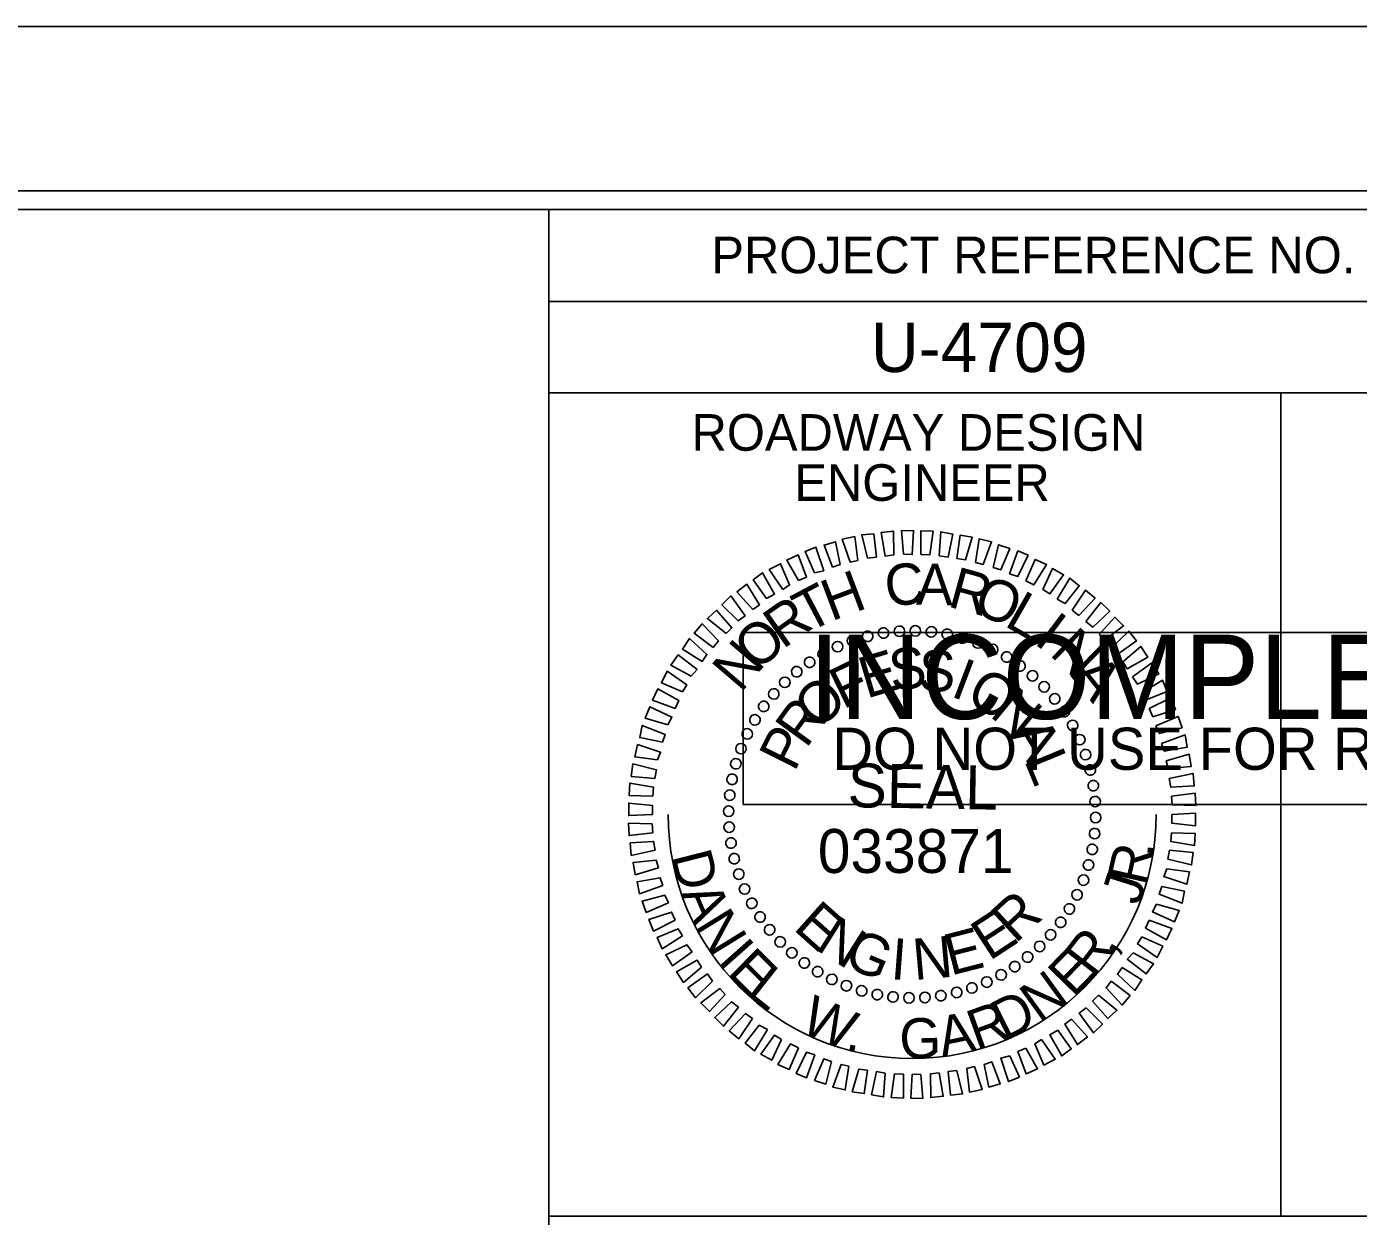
# Model space of a CAD drawing. Extents: x 958711 to 962106, y 831169 to 840840.
# Drawn here: x 960106.3 to 960288.4, y 840677.2 to 840839.7 of the extents above; entities that cross this region are included whole.
import ezdxf

# ---------------------------------------------------------------- set-up
doc = ezdxf.new("R2010")
doc.units = 0
for name, color, linetype in [('Scratch_Level_0', 7, 'Continuous'), ('Sheet Data Field CELL', 7, 'Continuous'), ('Sheet Plot Border Inside CELL', 7, 'Continuous'), ('Sheet Plot Border Outside CELL', 7, 'Continuous'), ('Sheet Professional Seal CELL', 7, 'Continuous'), ('Sheet Profile Grid Minor CELL', 7, 'Continuous'), ('Sheet Sticker Exception Certification CELL', 7, 'Continuous'), ('Sheet Sticker Incomplete CELL', 7, 'Continuous'), ('Sheet Typical CELL', 7, 'Continuous')]:
    doc.layers.add(name, color=color, linetype=linetype)

msp = doc.modelspace()

# ---------------------------------------------------------------- linework, layer by layer
at = {"layer": 'Scratch_Level_0'}
msp.add_arc((960227.41, 840732.08), 33.36, 180, 360, dxfattribs=at)
at = {"layer": 'Sheet Plot Border Inside CELL'}
msp.add_lwpolyline([(960390.3, 840817.27), (958723.8, 840817.27), (958723.8, 839762.17), (960390.3, 839762.17)], close=True, dxfattribs=at)
at = {"layer": 'Sheet Plot Border Outside CELL'}
msp.add_lwpolyline([(960394.8, 840839.72), (958710.8, 840839.72), (958710.8, 839739.72), (960394.8, 839739.72)], close=True, dxfattribs=at)
at = {"layer": 'Sheet Professional Seal CELL'}
for p, q in [((960221.31, 840756.43), (960221.31, 840756.43)), ((960223.51, 840756.83), (960223.51, 840756.83)), ((960225.66, 840757.13), (960225.66, 840757.13)), ((960227.86, 840757.18), (960227.86, 840757.18)), ((960230.06, 840757.03), (960230.06, 840757.03)), ((960232.21, 840756.68), (960232.21, 840756.68)), ((960217.21, 840755.03), (960217.21, 840755.03)), ((960219.21, 840755.83), (960219.21, 840755.83)), ((960234.31, 840756.23), (960234.31, 840756.23)), ((960236.41, 840755.53), (960236.41, 840755.53)), ((960238.41, 840754.63), (960238.41, 840754.63)), ((960213.36, 840752.88), (960213.36, 840752.88)), ((960215.26, 840754.03), (960215.26, 840754.03)), ((960240.36, 840753.63), (960240.36, 840753.63)), ((960211.61, 840751.63), (960211.61, 840751.63)), ((960242.16, 840752.38), (960242.16, 840752.38)), ((960243.91, 840751.03), (960243.91, 840751.03)), ((960209.96, 840750.13), (960209.96, 840750.13)), ((960245.46, 840749.53), (960245.46, 840749.53)), ((960208.46, 840748.58), (960208.46, 840748.58)), ((960246.96, 840747.88), (960246.96, 840747.88)), ((960207.11, 840746.83), (960207.11, 840746.83)), ((960248.21, 840746.13), (960248.21, 840746.13)), ((960205.86, 840745.03), (960205.86, 840745.03)), ((960249.36, 840744.23), (960249.36, 840744.23)), ((960204.86, 840743.08), (960204.86, 840743.08)), ((960250.36, 840742.28), (960250.36, 840742.28)), ((960203.96, 840741.08), (960203.96, 840741.08)), ((960251.16, 840740.28), (960251.16, 840740.28)), ((960203.26, 840738.98), (960203.26, 840738.98)), ((960251.76, 840738.18), (960251.76, 840738.18)), ((960202.81, 840736.88), (960202.81, 840736.88)), ((960202.46, 840734.73), (960202.46, 840734.73)), ((960252.16, 840735.98), (960252.16, 840735.98)), ((960252.46, 840733.83), (960252.46, 840733.83)), ((960202.31, 840732.53), (960202.31, 840732.53)), ((960227.41, 840732.08), (960227.41, 840732.08)), ((960252.51, 840731.63), (960252.51, 840731.63)), ((960202.36, 840730.33), (960202.36, 840730.33)), ((960252.36, 840729.43), (960252.36, 840729.43)), ((960202.66, 840728.18), (960202.66, 840728.18)), ((960252.01, 840727.28), (960252.01, 840727.28)), ((960203.06, 840725.98), (960203.06, 840725.98)), ((960203.66, 840723.88), (960203.66, 840723.88)), ((960251.56, 840725.18), (960251.56, 840725.18)), ((960204.46, 840721.88), (960204.46, 840721.88)), ((960250.86, 840723.08), (960250.86, 840723.08)), ((960205.46, 840719.93), (960205.46, 840719.93)), ((960249.96, 840721.08), (960249.96, 840721.08)), ((960206.61, 840718.03), (960206.61, 840718.03)), ((960248.96, 840719.13), (960248.96, 840719.13)), ((960207.86, 840716.28), (960207.86, 840716.28)), ((960247.71, 840717.33), (960247.71, 840717.33)), ((960209.36, 840714.63), (960209.36, 840714.63)), ((960246.36, 840715.58), (960246.36, 840715.58)), ((960210.91, 840713.13), (960210.91, 840713.13)), ((960244.86, 840714.03), (960244.86, 840714.03)), ((960212.66, 840711.78), (960212.66, 840711.78)), ((960241.46, 840711.28), (960241.46, 840711.28)), ((960243.21, 840712.53), (960243.21, 840712.53)), ((960214.46, 840710.53), (960214.46, 840710.53)), ((960216.41, 840709.53), (960216.41, 840709.53)), ((960237.61, 840709.13), (960237.61, 840709.13)), ((960239.56, 840710.13), (960239.56, 840710.13)), ((960218.41, 840708.63), (960218.41, 840708.63)), ((960220.51, 840707.93), (960220.51, 840707.93)), ((960222.61, 840707.48), (960222.61, 840707.48)), ((960224.76, 840707.13), (960224.76, 840707.13)), ((960231.31, 840707.33), (960231.31, 840707.33)), ((960233.51, 840707.73), (960233.51, 840707.73)), ((960235.61, 840708.33), (960235.61, 840708.33)), ((960226.96, 840706.98), (960226.96, 840706.98)), ((960229.16, 840707.03), (960229.16, 840707.03))]:
    msp.add_line(p, q, dxfattribs=at)
for points in [[(960226.21, 840767.63), (960225.96, 840770.88), (960227.61, 840770.83), (960227.41, 840767.58)], [(960228.61, 840767.58), (960228.61, 840770.83), (960230.26, 840770.78), (960229.81, 840767.53)], [(960216.51, 840765.88), (960215.36, 840768.88), (960216.91, 840769.33), (960217.56, 840766.23)], [(960218.91, 840766.53), (960217.86, 840769.68), (960219.56, 840770.03), (960219.96, 840766.78)], [(960221.31, 840767.08), (960220.51, 840770.28), (960222.16, 840770.43), (960222.51, 840767.23)], [(960223.71, 840767.38), (960223.16, 840770.58), (960224.86, 840770.78), (960224.91, 840767.53)], [(960231.11, 840767.43), (960231.31, 840770.68), (960232.96, 840770.38), (960232.31, 840767.23)], [(960233.51, 840767.03), (960233.96, 840770.23), (960235.61, 840769.98), (960234.71, 840766.88)], [(960236.06, 840766.48), (960236.56, 840769.73), (960238.26, 840769.33), (960237.11, 840766.23)], [(960211.86, 840764.03), (960210.26, 840766.83), (960211.81, 840767.53), (960212.96, 840764.48)], [(960214.06, 840765.08), (960212.76, 840767.98), (960214.26, 840768.58), (960215.31, 840765.38)], [(960238.46, 840765.83), (960239.21, 840768.93), (960240.76, 840768.43), (960239.51, 840765.48)], [(960240.71, 840764.93), (960241.86, 840768.08), (960243.26, 840767.48), (960241.86, 840764.58)], [(960209.71, 840762.83), (960207.86, 840765.53), (960209.41, 840766.33), (960210.66, 840763.43)], [(960242.96, 840763.98), (960244.21, 840766.93), (960245.76, 840766.23), (960244.06, 840763.43)], [(960245.26, 840762.83), (960246.61, 840765.68), (960248.11, 840764.83), (960246.21, 840762.23)], [(960205.61, 840760.08), (960203.46, 840762.48), (960204.81, 840763.53), (960206.56, 840760.73)], [(960207.51, 840761.58), (960205.66, 840764.13), (960206.96, 840765.08), (960208.61, 840762.18)], [(960247.21, 840761.48), (960248.96, 840764.38), (960250.26, 840763.33), (960248.31, 840760.88)], [(960203.61, 840758.53), (960201.41, 840760.73), (960202.61, 840761.93), (960204.56, 840759.23)], [(960249.26, 840759.98), (960251.11, 840762.73), (960252.41, 840761.63), (960250.21, 840759.28)], [(960201.96, 840756.78), (960199.41, 840758.83), (960200.66, 840759.98), (960202.76, 840757.58)], [(960251.16, 840758.43), (960253.21, 840761.03), (960254.41, 840759.83), (960252.11, 840757.68)], [(960200.21, 840754.88), (960197.61, 840756.83), (960198.71, 840758.13), (960200.91, 840755.78)], [(960252.96, 840756.68), (960255.11, 840759.03), (960256.31, 840757.83), (960253.71, 840755.88)], [(960254.71, 840754.88), (960257.01, 840757.13), (960258.06, 840755.78), (960255.41, 840753.88)], [(960198.71, 840752.98), (960196.01, 840754.68), (960196.96, 840756.13), (960199.36, 840753.93)], [(960256.21, 840752.93), (960258.66, 840755.03), (960259.61, 840753.58), (960256.81, 840751.98)], [(960197.21, 840750.98), (960194.41, 840752.48), (960195.41, 840753.88), (960198.01, 840751.88)], [(960257.51, 840750.88), (960260.16, 840752.78), (960261.11, 840751.28), (960258.21, 840749.88)], [(960196.01, 840748.83), (960193.16, 840750.08), (960193.91, 840751.63), (960196.61, 840749.78)], [(960195.01, 840746.53), (960191.91, 840747.68), (960192.66, 840749.23), (960195.51, 840747.63)], [(960258.81, 840748.68), (960261.61, 840750.43), (960262.26, 840748.88), (960259.41, 840747.73)], [(960259.81, 840746.53), (960262.76, 840748.03), (960263.41, 840746.43), (960260.31, 840745.43)], [(960194.01, 840744.33), (960190.91, 840745.23), (960191.56, 840746.78), (960194.56, 840745.38)], [(960260.71, 840744.18), (960263.76, 840745.48), (960264.31, 840743.93), (960261.21, 840743.13)], [(960193.26, 840741.93), (960190.16, 840742.58), (960190.51, 840744.23), (960193.66, 840742.98)], [(960261.51, 840741.78), (960264.71, 840742.93), (960265.01, 840741.28), (960261.86, 840740.73)], [(960192.61, 840739.53), (960189.51, 840739.93), (960189.86, 840741.63), (960193.01, 840740.58)], [(960262.11, 840739.38), (960265.26, 840740.33), (960265.56, 840738.63), (960262.41, 840738.33)], [(960192.21, 840736.98), (960189.01, 840737.28), (960189.21, 840738.98), (960192.46, 840738.18)], [(960191.96, 840734.58), (960188.71, 840734.68), (960188.81, 840736.33), (960192.06, 840735.78)], [(960262.56, 840736.98), (960265.81, 840737.68), (960265.96, 840735.98), (960262.76, 840735.78)], [(960262.86, 840734.58), (960266.11, 840734.98), (960266.21, 840733.28), (960262.96, 840733.38)], [(960191.91, 840732.08), (960188.66, 840731.93), (960188.66, 840733.63), (960191.91, 840733.28)], [(960191.96, 840729.58), (960188.71, 840729.18), (960188.61, 840730.88), (960191.86, 840730.78)], [(960262.91, 840732.08), (960266.16, 840732.23), (960266.16, 840730.53), (960262.91, 840730.88)], [(960262.86, 840729.58), (960266.11, 840729.48), (960266.01, 840727.83), (960262.76, 840728.38)], [(960192.26, 840727.18), (960189.01, 840726.48), (960188.86, 840728.18), (960192.06, 840728.38)], [(960262.61, 840727.18), (960265.81, 840726.88), (960265.61, 840725.18), (960262.36, 840725.98)], [(960192.71, 840724.78), (960189.56, 840723.83), (960189.26, 840725.53), (960192.41, 840725.83)], [(960262.21, 840724.63), (960265.31, 840724.23), (960264.96, 840722.53), (960261.81, 840723.58)], [(960193.31, 840722.38), (960190.11, 840721.23), (960189.81, 840722.88), (960192.96, 840723.43)], [(960261.56, 840722.23), (960264.66, 840721.58), (960264.31, 840719.93), (960261.16, 840721.18)], [(960194.11, 840719.98), (960191.06, 840718.68), (960190.51, 840720.23), (960193.61, 840721.03)], [(960260.81, 840719.83), (960263.91, 840718.93), (960263.26, 840717.38), (960260.26, 840718.78)], [(960195.01, 840717.63), (960192.06, 840716.13), (960191.41, 840717.73), (960194.51, 840718.73)], [(960196.01, 840715.48), (960193.21, 840713.73), (960192.56, 840715.28), (960195.41, 840716.43)], [(960259.81, 840717.63), (960262.91, 840716.48), (960262.16, 840714.93), (960259.31, 840716.53)], [(960258.81, 840715.33), (960261.66, 840714.08), (960260.91, 840712.53), (960258.21, 840714.38)], [(960197.31, 840713.28), (960194.66, 840711.38), (960193.71, 840712.88), (960196.61, 840714.28)], [(960257.61, 840713.18), (960260.41, 840711.68), (960259.41, 840710.28), (960256.81, 840712.28)], [(960198.61, 840711.23), (960196.16, 840709.13), (960195.21, 840710.58), (960198.01, 840712.18)], [(960256.11, 840711.18), (960258.81, 840709.48), (960257.86, 840708.03), (960255.46, 840710.23)], [(960200.11, 840709.28), (960197.81, 840707.03), (960196.76, 840708.38), (960199.41, 840710.28)], [(960254.61, 840709.28), (960257.21, 840707.33), (960256.11, 840706.03), (960253.91, 840708.38)], [(960201.86, 840707.48), (960199.71, 840705.13), (960198.51, 840706.33), (960201.11, 840708.28)], [(960252.86, 840707.38), (960255.41, 840705.33), (960254.16, 840704.18), (960252.06, 840706.58)], [(960203.66, 840705.73), (960201.61, 840703.13), (960200.41, 840704.33), (960202.71, 840706.48)], [(960251.21, 840705.63), (960253.41, 840703.43), (960252.21, 840702.23), (960250.26, 840704.93)], [(960205.56, 840704.18), (960203.71, 840701.43), (960202.41, 840702.53), (960204.61, 840704.88)], [(960249.21, 840704.08), (960251.36, 840701.68), (960250.01, 840700.63), (960248.26, 840703.43)], [(960207.61, 840702.68), (960205.86, 840699.78), (960204.56, 840700.83), (960206.51, 840703.28)], [(960209.56, 840701.33), (960208.21, 840698.48), (960206.71, 840699.33), (960208.61, 840701.93)], [(960247.31, 840702.58), (960249.16, 840700.03), (960247.86, 840699.08), (960246.21, 840701.98)], [(960211.86, 840700.18), (960210.61, 840697.23), (960209.06, 840697.93), (960210.76, 840700.73)], [(960242.96, 840700.13), (960244.56, 840697.33), (960243.01, 840696.63), (960241.86, 840699.68)], [(960245.11, 840701.33), (960246.96, 840698.63), (960245.41, 840697.83), (960244.16, 840700.73)], [(960214.11, 840699.23), (960212.96, 840696.08), (960211.56, 840696.68), (960212.96, 840699.58)], [(960216.36, 840698.33), (960215.61, 840695.23), (960214.06, 840695.73), (960215.31, 840698.68)], [(960238.31, 840698.28), (960239.46, 840695.28), (960237.91, 840694.83), (960237.26, 840697.93)], [(960240.76, 840699.08), (960242.06, 840696.18), (960240.56, 840695.58), (960239.51, 840698.78)], [(960218.76, 840697.68), (960218.26, 840694.43), (960216.56, 840694.83), (960217.71, 840697.93)], [(960221.31, 840697.13), (960220.86, 840693.93), (960219.21, 840694.18), (960220.11, 840697.28)], [(960223.71, 840696.73), (960223.51, 840693.48), (960221.86, 840693.78), (960222.51, 840696.93)], [(960226.21, 840696.58), (960226.21, 840693.33), (960224.56, 840693.38), (960225.01, 840696.63)], [(960228.61, 840696.53), (960228.86, 840693.28), (960227.21, 840693.33), (960227.41, 840696.58)], [(960231.11, 840696.78), (960231.66, 840693.58), (960229.96, 840693.38), (960229.91, 840696.63)], [(960233.51, 840697.08), (960234.31, 840693.88), (960232.66, 840693.73), (960232.31, 840696.93)], [(960235.91, 840697.63), (960236.96, 840694.48), (960235.26, 840694.13), (960234.86, 840697.38)]]:
    msp.add_lwpolyline(points, close=True, dxfattribs=at)
for centre, major_axis in [((960219.25, 840755.8), (-0.234, 0.681)), ((960221.34, 840756.42), (-0.174, 0.699)), ((960223.49, 840756.86), (-0.113, 0.711)), ((960225.66, 840757.1), (-0.05, 0.718)), ((960227.85, 840757.16), (0.013, 0.72)), ((960230.03, 840757.03), (0.075, 0.716)), ((960232.2, 840756.7), (0.137, 0.707)), ((960234.32, 840756.19), (0.198, 0.692)), ((960236.4, 840755.5), (0.258, 0.672)), ((960215.25, 840754.02), (-0.349, 0.63)), ((960217.21, 840755), (-0.293, 0.658)), ((960238.41, 840754.63), (0.316, 0.647)), ((960213.39, 840752.88), (-0.403, 0.597)), ((960240.33, 840753.58), (0.371, 0.617)), ((960242.15, 840752.37), (0.423, 0.582)), ((960209.99, 840750.13), (-0.5, 0.518)), ((960211.63, 840751.58), (-0.453, 0.56)), ((960243.87, 840751.01), (0.472, 0.543)), ((960208.48, 840748.54), (-0.543, 0.472)), ((960245.45, 840749.51), (0.518, 0.5)), ((960207.12, 840746.83), (-0.582, 0.423)), ((960246.9, 840747.87), (0.56, 0.453)), ((960205.91, 840745), (-0.617, 0.371)), ((960248.2, 840746.11), (0.597, 0.403)), ((960204.87, 840743.08), (-0.647, 0.316)), ((960249.35, 840744.24), (0.63, 0.349)), ((960204, 840741.07), (-0.672, 0.258)), ((960250.32, 840742.29), (0.658, 0.293)), ((960251.12, 840740.25), (0.681, 0.234)), ((960203.3, 840739), (-0.692, 0.198)), ((960251.75, 840738.15), (0.699, 0.174)), ((960202.79, 840736.87), (-0.707, 0.137)), ((960252.18, 840736.01), (0.711, 0.113)), ((960202.47, 840734.71), (-0.716, 0.075)), ((960252.43, 840733.83), (0.718, 0.05)), ((960202.33, 840732.52), (-0.72, 0.013)), ((960202.39, 840730.33), (-0.718, -0.05)), ((960252.49, 840731.65), (0.72, -0.013)), ((960202.64, 840728.16), (-0.711, -0.113)), ((960252.35, 840729.46), (0.716, -0.075)), ((960252.03, 840727.3), (0.707, -0.137)), ((960203.08, 840726.02), (-0.699, -0.174)), ((960251.52, 840725.17), (0.692, -0.198)), ((960203.7, 840723.92), (-0.681, -0.234)), ((960250.83, 840723.1), (0.672, -0.258)), ((960204.5, 840721.88), (-0.658, -0.293)), ((960249.95, 840721.09), (0.647, -0.316)), ((960205.48, 840719.93), (-0.63, -0.349)), ((960248.91, 840719.17), (0.617, -0.371)), ((960206.62, 840718.06), (-0.597, -0.403)), ((960247.7, 840717.34), (0.582, -0.423)), ((960207.92, 840716.3), (-0.56, -0.453)), ((960246.34, 840715.63), (0.543, -0.472)), ((960209.37, 840714.66), (-0.518, -0.5)), ((960244.83, 840714.04), (0.5, -0.518)), ((960210.96, 840713.16), (-0.472, -0.543)), ((960212.67, 840711.79), (-0.423, -0.582)), ((960243.19, 840712.59), (0.453, -0.56)), ((960214.49, 840710.59), (-0.371, -0.617)), ((960239.57, 840710.15), (0.349, -0.63)), ((960241.44, 840711.29), (0.403, -0.597)), ((960216.42, 840709.54), (-0.316, -0.647)), ((960218.42, 840708.67), (-0.258, -0.672)), ((960235.58, 840708.37), (0.234, -0.681)), ((960237.61, 840709.17), (0.293, -0.658)), ((960220.5, 840707.98), (-0.198, -0.692)), ((960222.63, 840707.47), (-0.137, -0.707)), ((960224.79, 840707.14), (-0.075, -0.716)), ((960226.97, 840707.01), (-0.013, -0.72)), ((960229.16, 840707.07), (0.05, -0.718)), ((960231.33, 840707.31), (0.113, -0.711)), ((960233.48, 840707.75), (0.174, -0.699))]:
    msp.add_ellipse(centre, major_axis=major_axis, ratio=0.999708, dxfattribs=at)
at = {"layer": 'Sheet Sticker Exception Certification CELL'}
for p, q in [((960177.75, 840653.67), (960177.75, 840677.17)), ((960177.75, 840677.17), (960377.79, 840677.17))]:
    msp.add_line(p, q, dxfattribs=at)
at = {"layer": 'Sheet Sticker Incomplete CELL'}
msp.add_lwpolyline([(960204.3, 840733.42), (960204.3, 840756.92), (960351.3, 840756.92), (960351.3, 840733.42)], close=True, dxfattribs=at)
at = {"layer": 'Sheet Typical CELL'}
for p, q in [((960177.75, 840802.17), (960377.8, 840802.17)), ((960277.8, 840789.67), (960277.8, 840677.22))]:
    msp.add_line(p, q, dxfattribs=at)
for points in [[(960377.8, 840814.72), (958877.8, 840814.72), (958877.8, 839764.72), (960377.8, 839764.72)], [(960177.75, 840814.72), (960377.8, 840814.72), (960377.8, 840789.67), (960177.75, 840789.67)], [(960177.75, 840789.67), (960277.8, 840789.67), (960277.8, 840677.17), (960177.75, 840677.17)], [(960277.8, 840789.67), (960377.8, 840789.67), (960377.8, 840677.17), (960277.8, 840677.17)]]:
    msp.add_lwpolyline(points, close=True, dxfattribs=at)

# ---------------------------------------------------------------- texts
at = {"layer": 'Sheet Data Field CELL'}
msp.add_text('U-4709', height=6.75, dxfattribs=at).set_placement((960221.78, 840792.52))
at = {"layer": 'Sheet Professional Seal CELL'}
for s, height, rotation, p in [('H', 5.64, 20.6195, (960216.36, 840758.43)), ('C', 5.64, 6.2199, (960223.96, 840760.43)), ('A', 5.64, 359.0203, (960227.91, 840760.73)), ('R', 5.64, 344.6211, (960232.11, 840760.53)), ('T', 5.64, 27.8198, (960213.11, 840756.78)), ('O', 5.64, 337.4212, (960235.46, 840759.78)), ('L', 5.64, 330.2209, (960239.86, 840757.93)), ('R', 5.64, 35.0205, (960209.71, 840754.58)), ('O', 5.64, 42.2217, (960206.26, 840751.48)), ('I', 5.64, 323.0201, (960243.91, 840755.53)), ('N', 5.64, 315.8189, (960246.06, 840753.98)), ('N', 5.64, 49.4235, (960203.96, 840748.58)), ('E', 5.64, 16.6111, (960221.16, 840747.88)), ('S', 5.64, 7.2556, (960224.61, 840748.93)), ('S', 5.64, 357.9004, (960228.21, 840748.98)), ('F', 5.64, 25.967, (960217.96, 840746.38)), ('I', 5.64, 339.1896, (960232.51, 840748.28)), ('A', 5.64, 308.6172, (960249.01, 840751.03)), ('O', 5.64, 329.8335, (960234.51, 840747.58)), ('O', 5.64, 44.6812, (960214.66, 840743.43)), ('N', 5.64, 320.4766, (960237.86, 840745.58)), ('R', 5.64, 54.0397, (960212.91, 840740.98)), ('P', 5.64, 63.3989, (960211.31, 840737.78)), ('A', 5.64, 301.7603, (960240.71, 840742.98)), ('L', 5.64, 292.4008, (960242.66, 840739.53)), ('SEAL', 5.998, 359, (960218.56, 840733.08)), ('E', 5.64, 318.2769, (960211.01, 840716.43)), ('R', 5.64, 42.4814, (960241.51, 840714.33)), ('N', 5.64, 327.634, (960214.01, 840713.73)), ('E', 5.64, 33.1241, (960237.96, 840711.98)), ('E', 5.64, 14.4118, (960232.66, 840710.03)), ('G', 5.64, 336.9902, (960217.81, 840711.48)), ('I', 5.64, 355.7012, (960224.36, 840709.58)), ('N', 5.64, 5.0564, (960227.71, 840709.43))]:
    msp.add_text(s, height=height, rotation=rotation, dxfattribs=at).set_placement(p)
at = {"layer": 'Sheet Profile Grid Minor CELL'}
msp.add_text('033871', height=5.998, dxfattribs=at).set_placement((960214.51, 840724.08))
for s, rotation, p in [('D', 284.2682, (960194.42, 840726.44)), ('R', 77.3541, (960259.38, 840722.18)), ('.', 84.2805, (960260.34, 840726.11)), ('J', 72.4855, (960258.43, 840719.5)), ('A', 293.4128, (960195.74, 840721.27)), ('N', 301.5986, (960197.6, 840716.87)), ('R', 52.3788, (960252.21, 840709.61)), ('I', 311.5304, (960200.67, 840711.96)), (',', 59.3052, (960254.74, 840712.76)), ('E', 315.0508, (960201.96, 840710.35)), ('E', 45.7958, (960249.47, 840706.91)), ('L', 321.6338, (960204.62, 840707.58)), ('N', 35.8641, (960244.8, 840703.49)), ('W', 336.8891, (960211.87, 840702.44)), ('D', 26.7195, (960240.03, 840701.09)), ('R', 19.793, (960236.2, 840699.79)), ('G', 1.6755, (960225.73, 840698.66)), ('A', 11.6072, (960231.52, 840698.87)), ('.', 348.4952, (960218.15, 840699.92))]:
    msp.add_text(s, height=5.5, rotation=rotation, dxfattribs=at).set_placement(p)
at = {"layer": 'Sheet Sticker Incomplete CELL'}
for s, height, p in [('INCOMPLETE PLANS', 11.52, (960213.25, 840745.12)), ('DO NOT USE FOR R/W ACQUISITION', 5.76, (960216.5, 840738.17))]:
    msp.add_text(s, height=height, dxfattribs=at).set_placement(p)
at = {"layer": 'Sheet Typical CELL'}
for s, height, p in [('PROJECT REFERENCE NO.', 5.0001, (960199.95, 840806.02)), ('ROADWAY DESIGN', 5.0001, (960197.25, 840781.77)), ('ENGINEER', 5, (960211.3, 840774.92))]:
    msp.add_text(s, height=height, dxfattribs=at).set_placement(p)

doc.saveas('drawing.dxf')
